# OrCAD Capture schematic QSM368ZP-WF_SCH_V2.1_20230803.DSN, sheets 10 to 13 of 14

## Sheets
10 PAGE11-UART&CAN: size A2
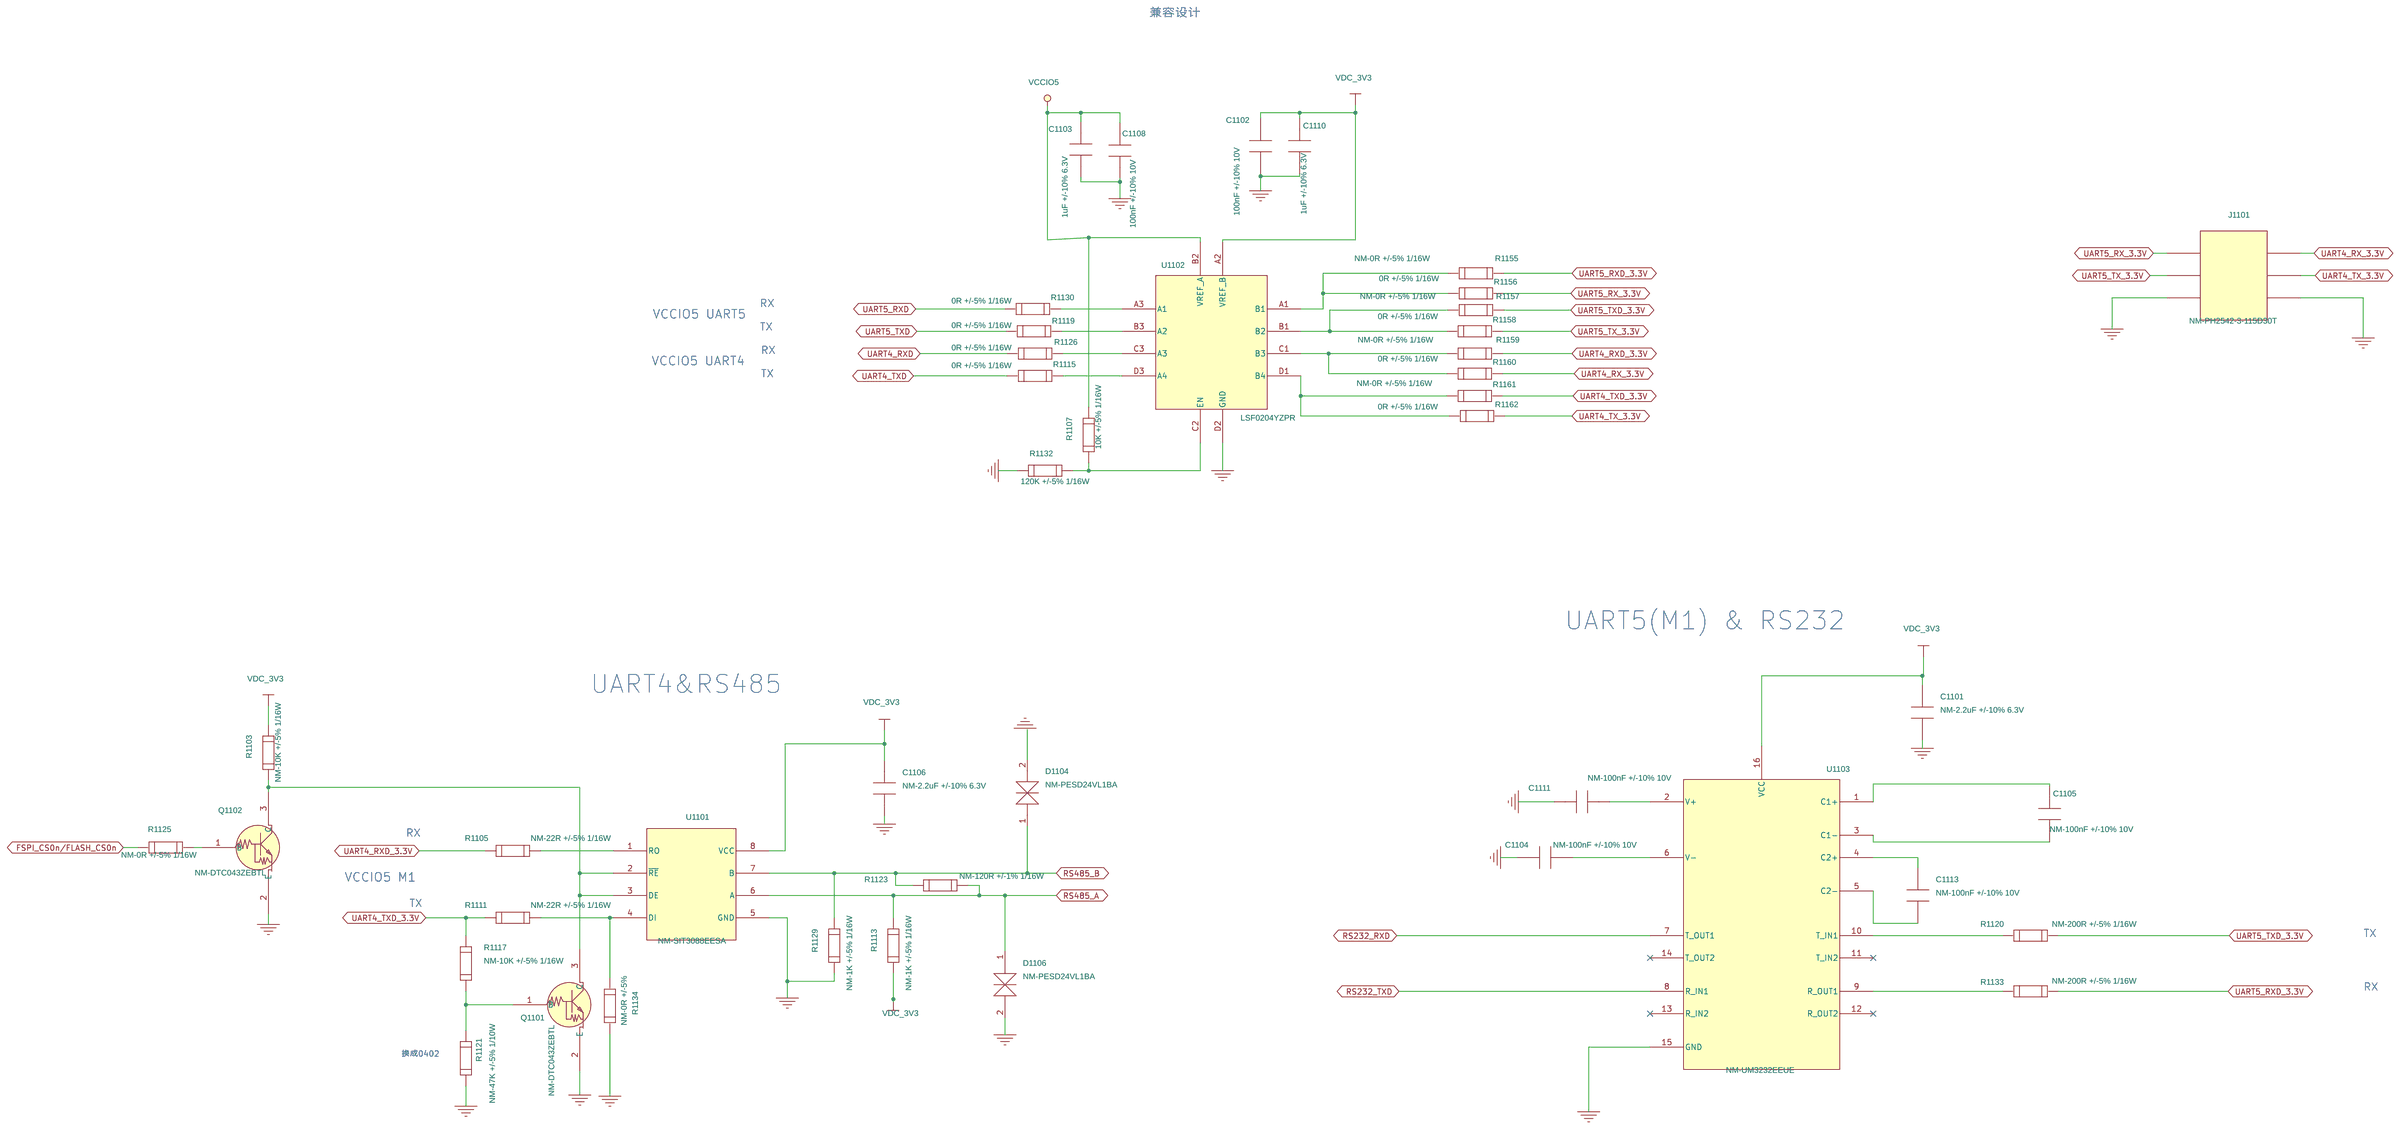
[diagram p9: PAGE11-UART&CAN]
11 PAGE12-RTC&KEY: size A3
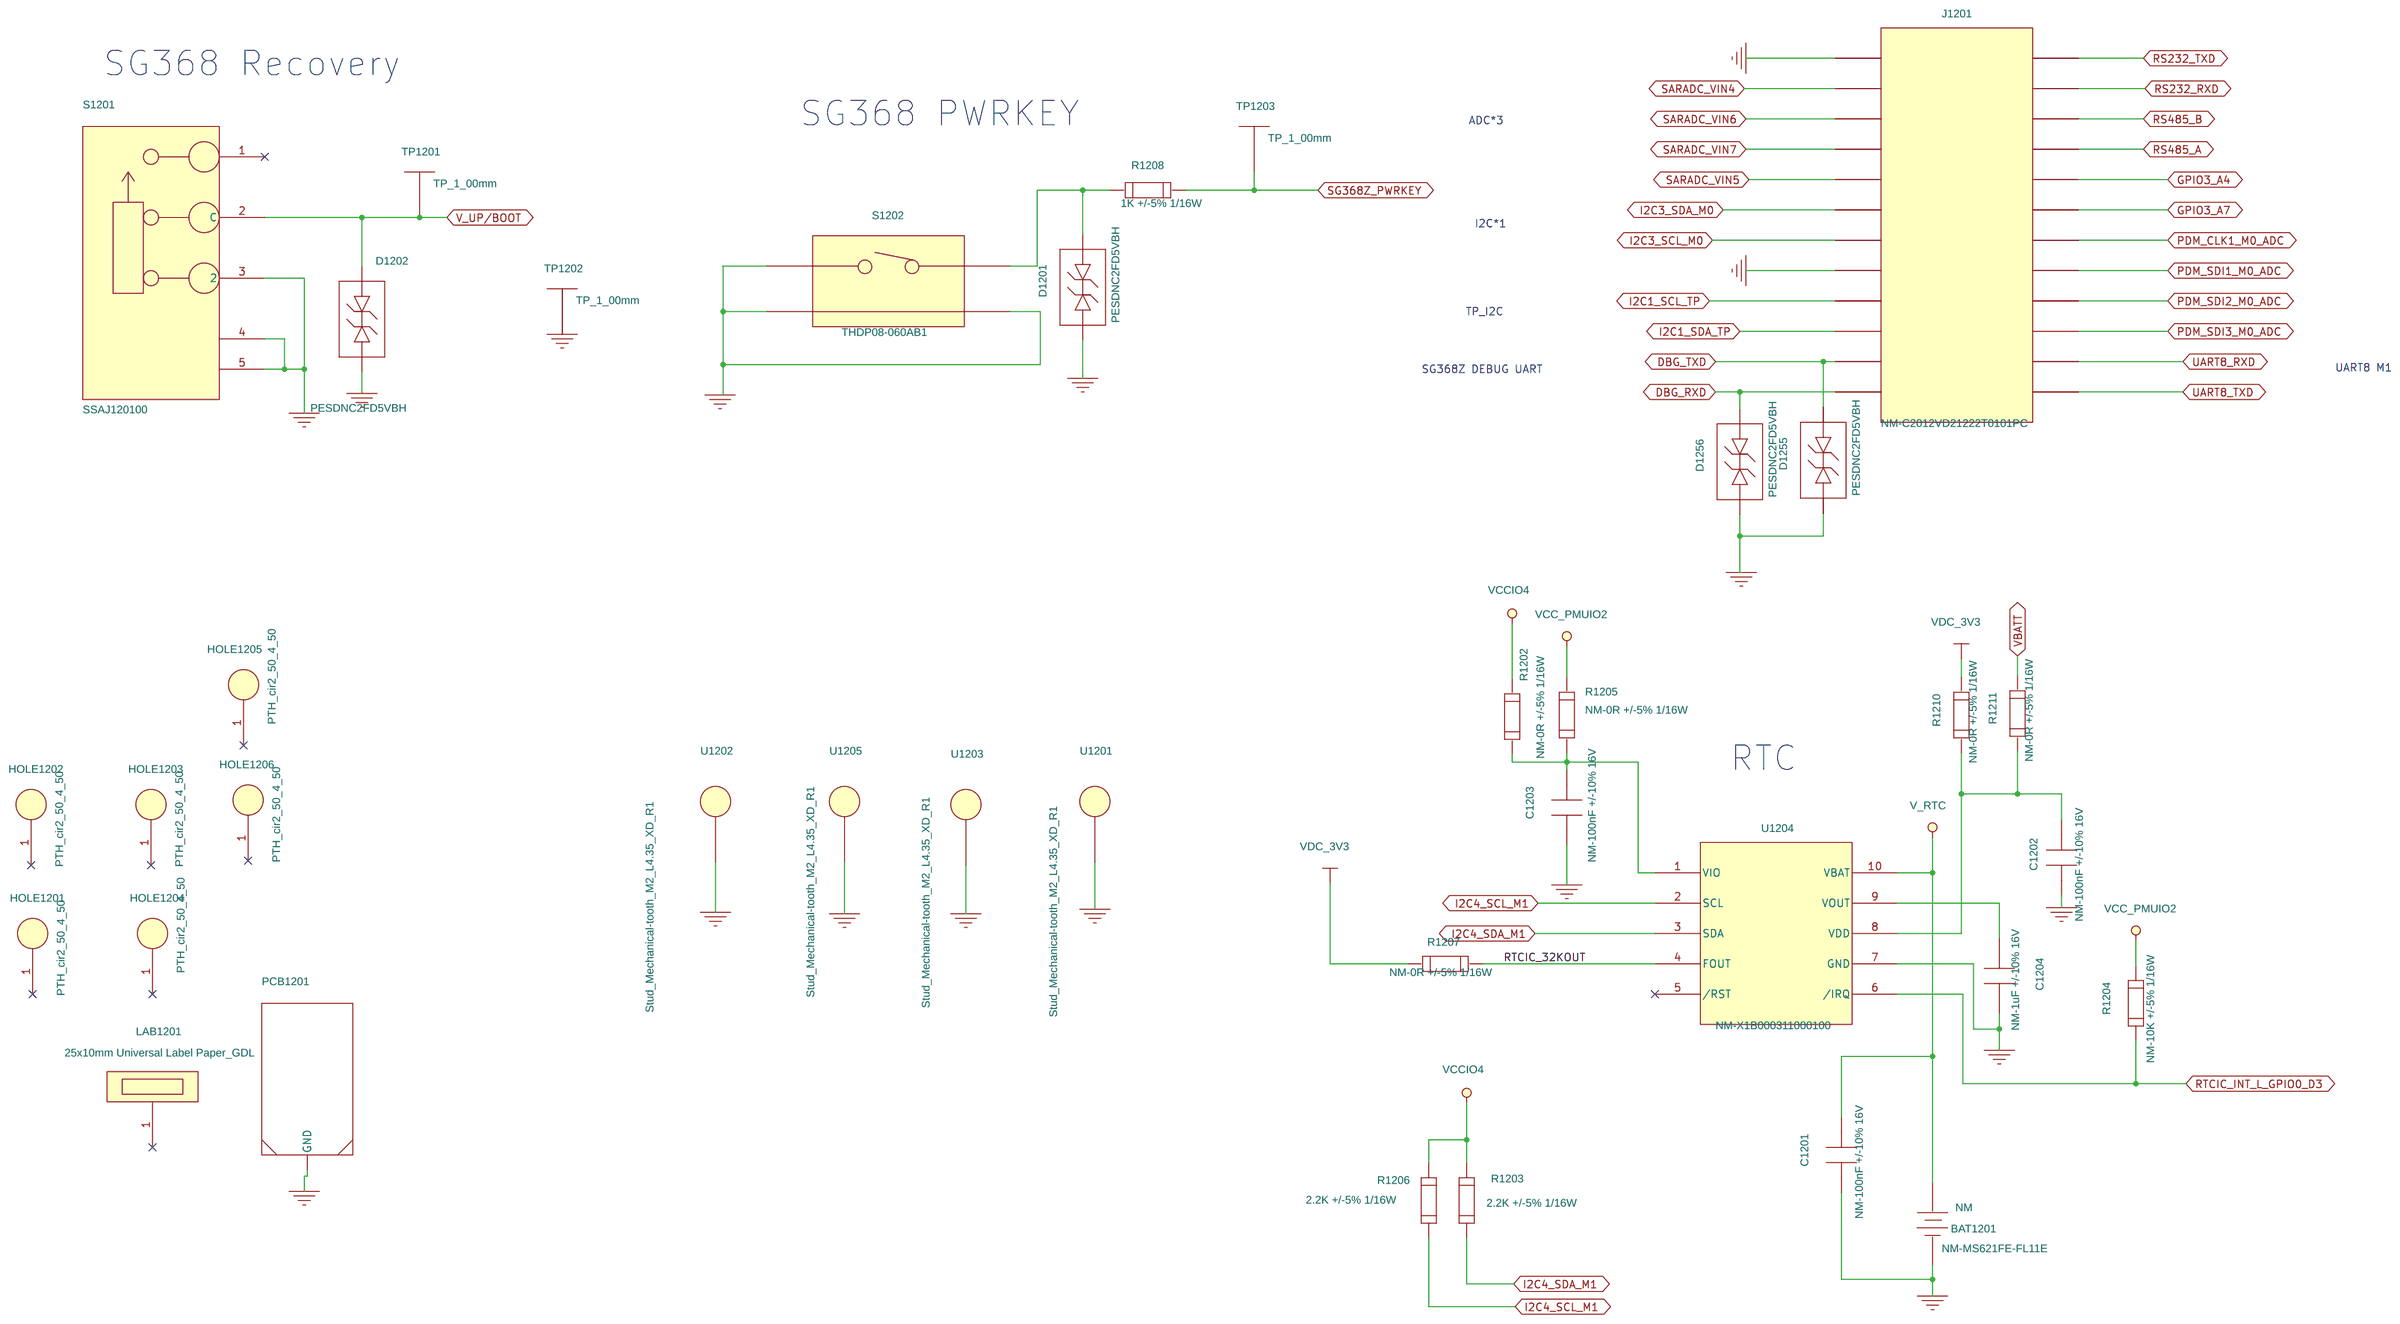
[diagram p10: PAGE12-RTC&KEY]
12 PAGE13-Module1: size A2
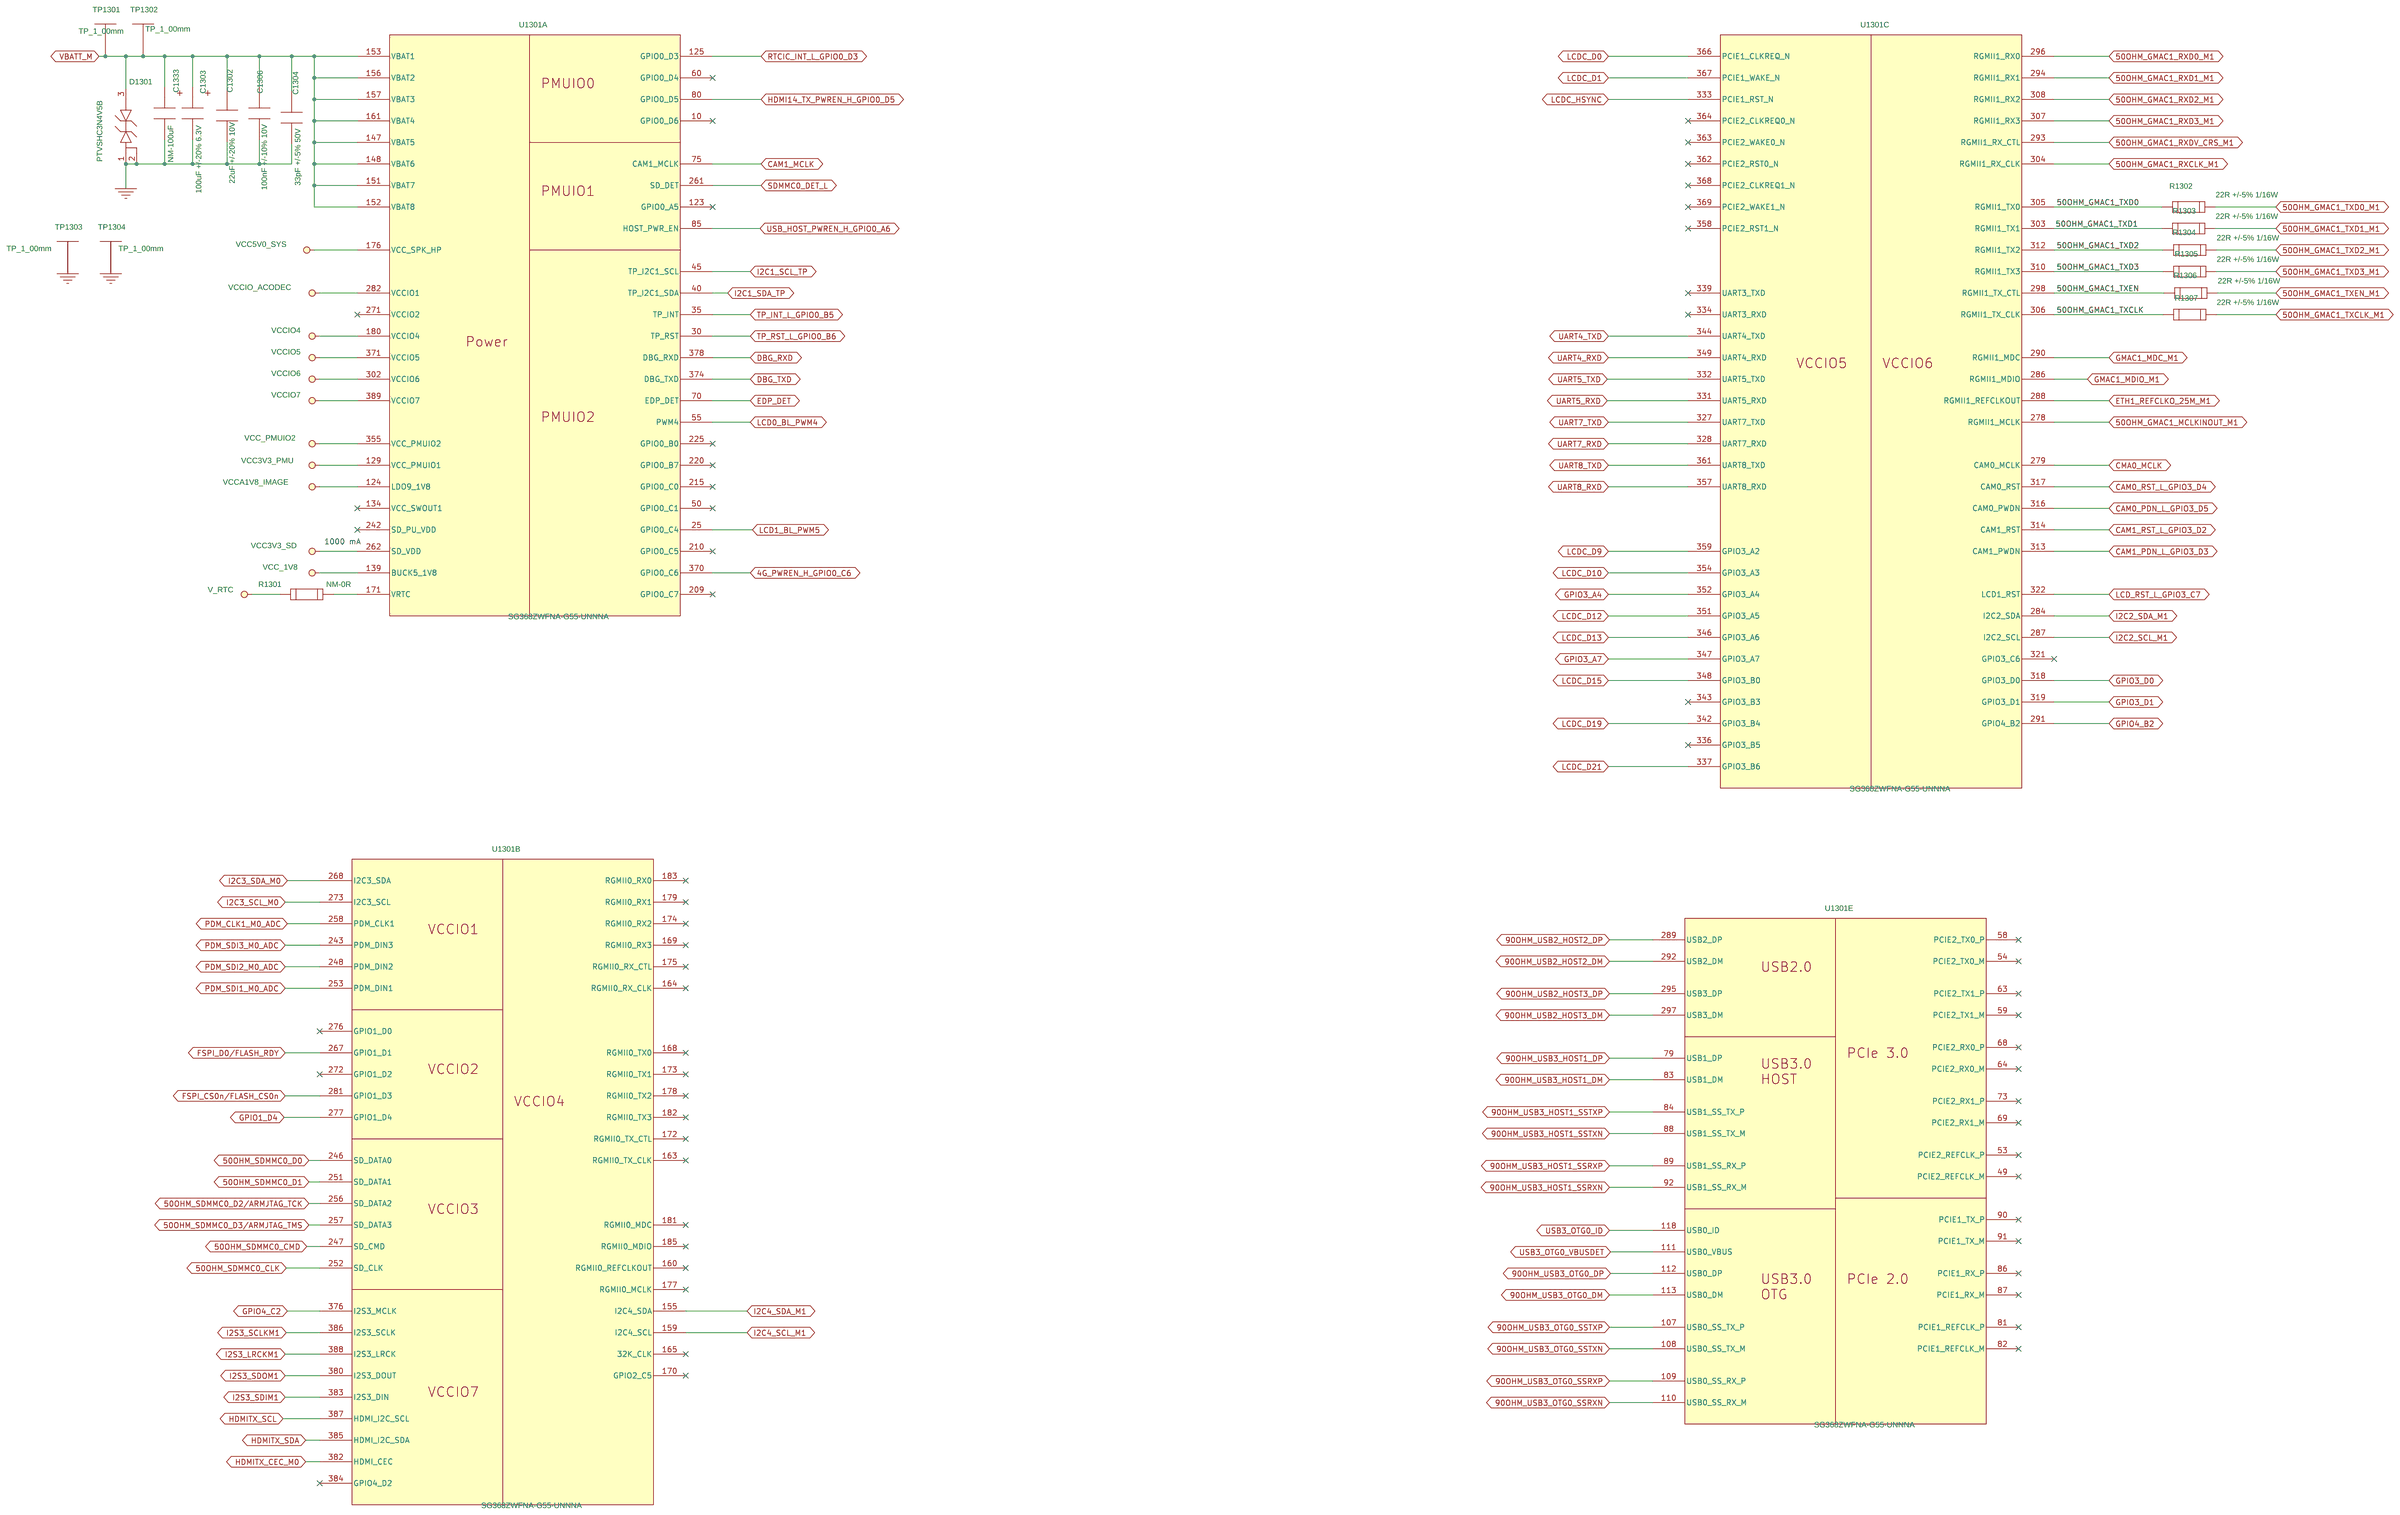
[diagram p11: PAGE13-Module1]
13 PAGE14-Module2: size A2
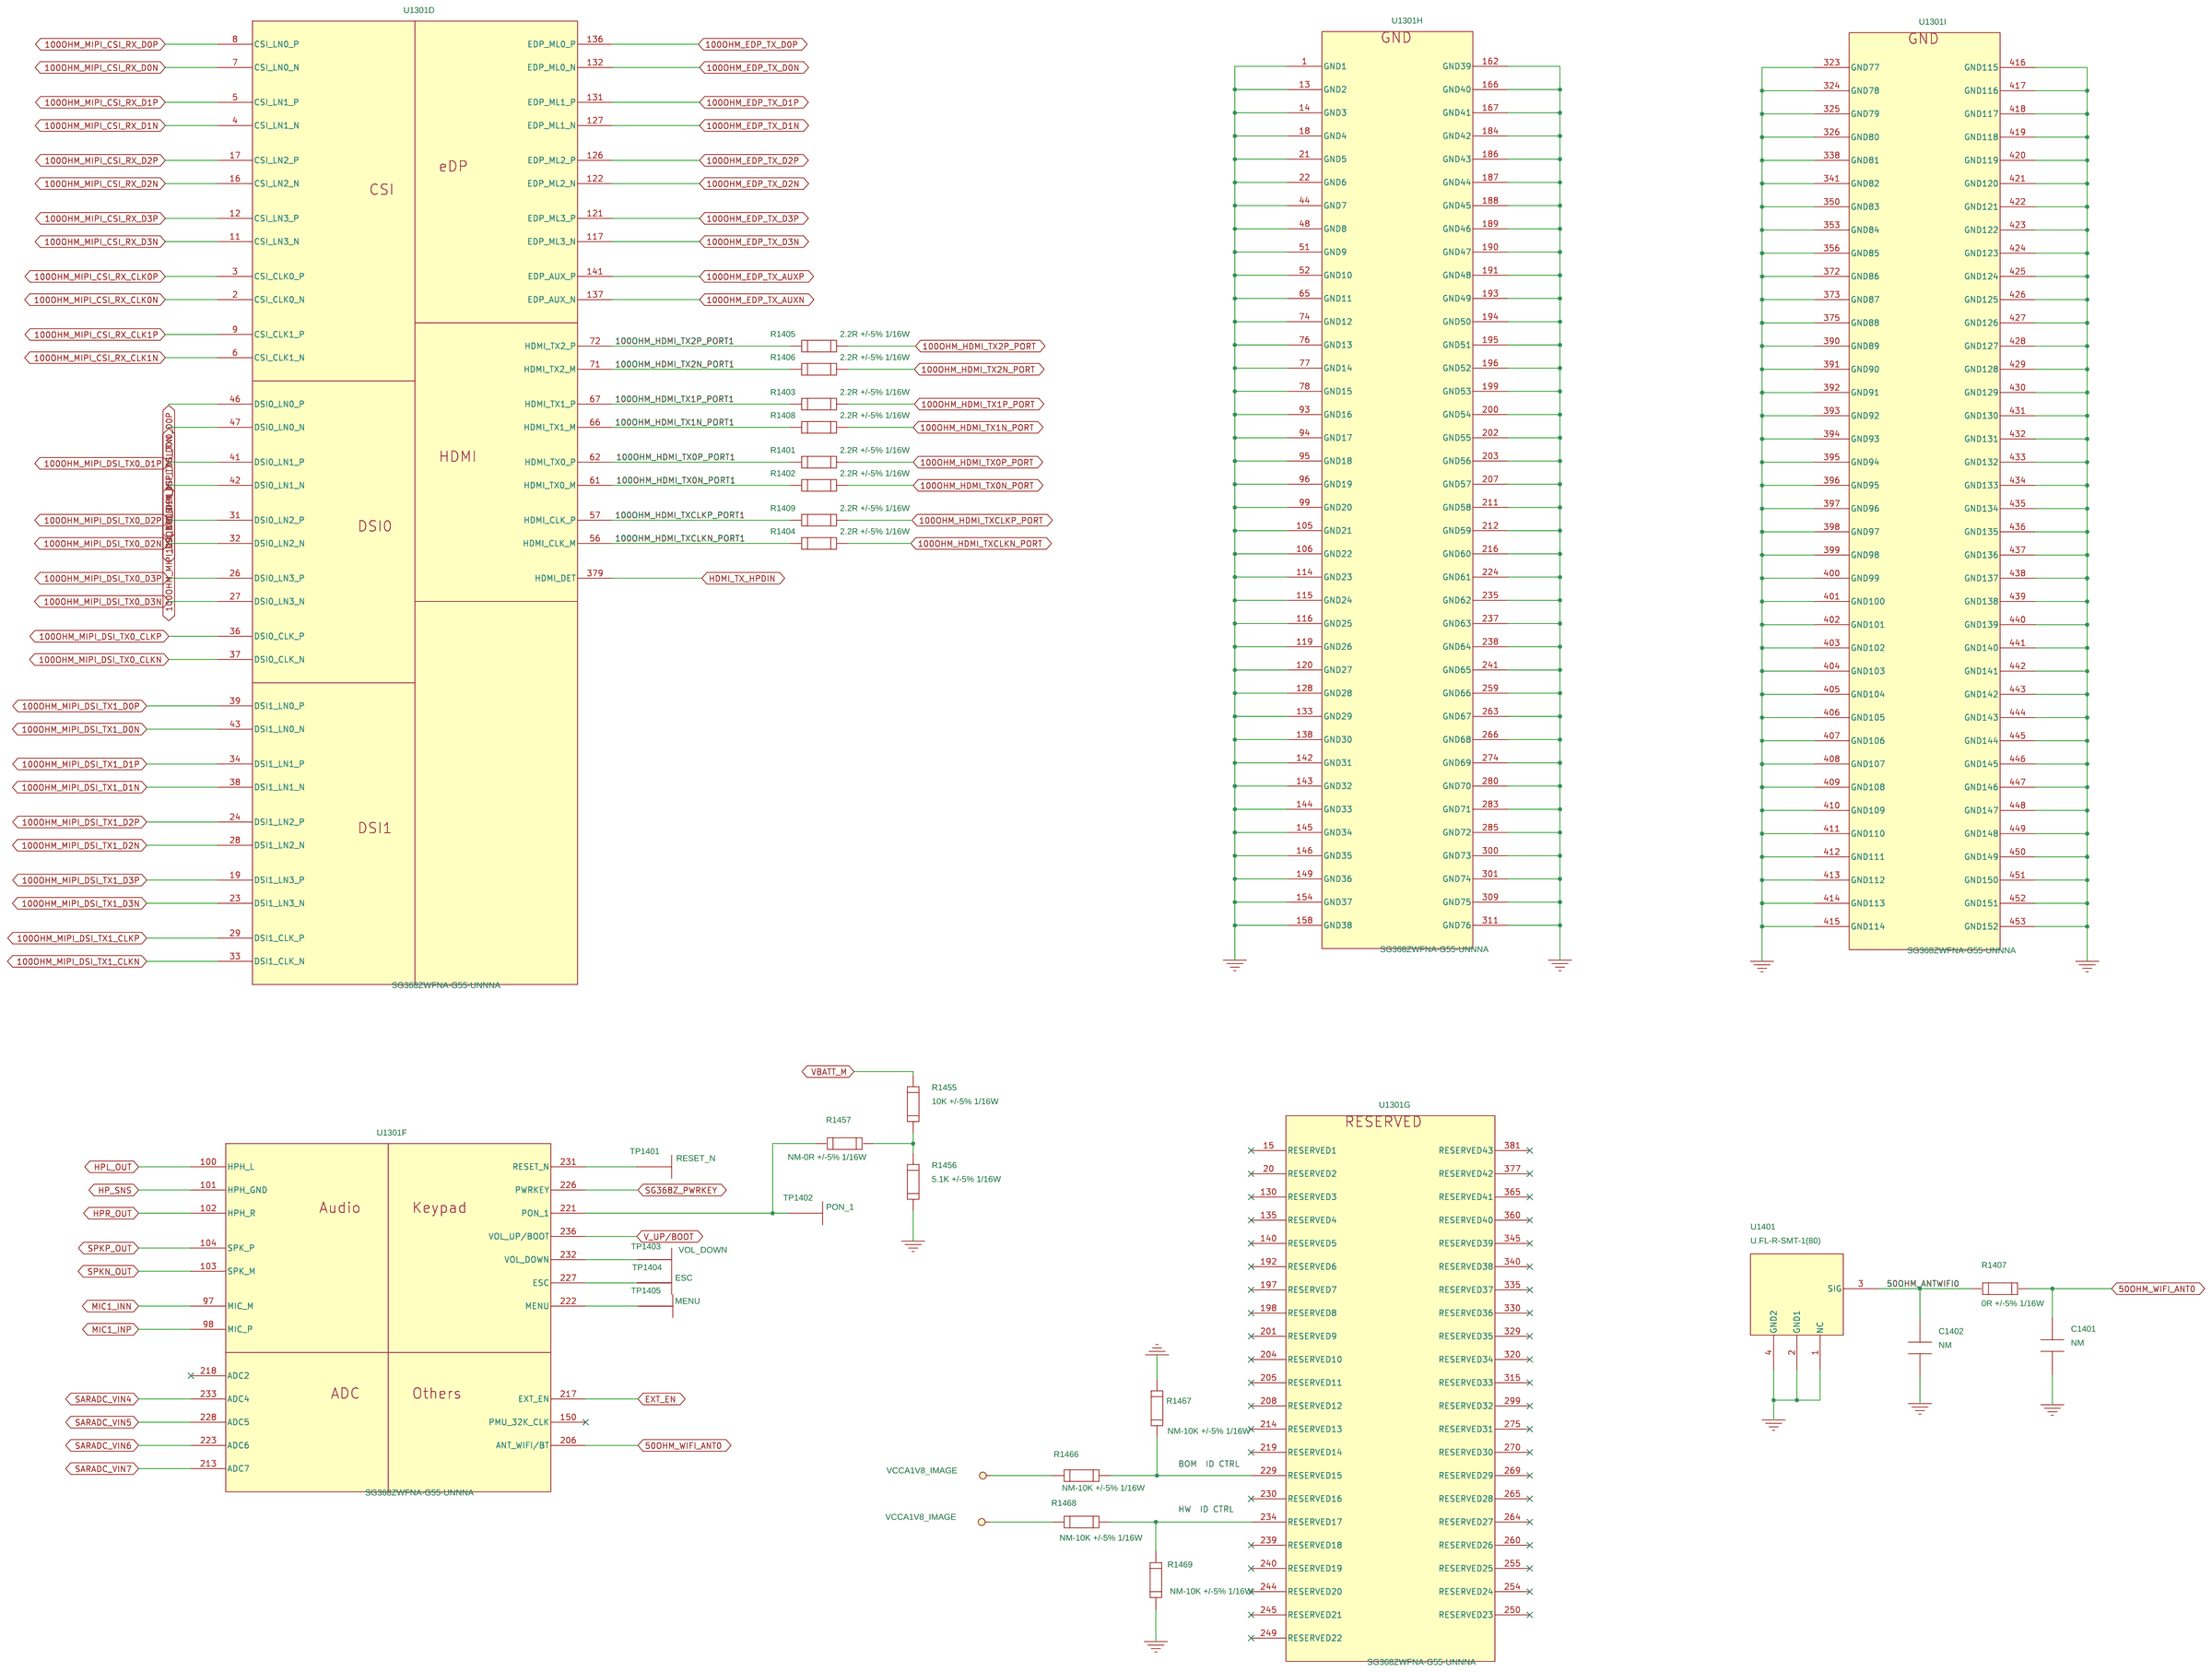
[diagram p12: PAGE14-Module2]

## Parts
sheet PAGE11-UART&CAN
C1101  NM-2.2uF +/-10% 6.3V  [c-0402]
C1102  100nF +/-10% 10V  [C-0402]
C1103  1uF +/-10% 6.3V  [C-0402]
C1104  NM-100nF +/-10% 10V  [C-0402]
C1105  NM-100nF +/-10% 10V  [C-0402]
C1106  NM-2.2uF +/-10% 6.3V  [c-0402]
C1108  100nF +/-10% 10V  [C-0402]
C1110  1uF +/-10% 6.3V  [C-0402]
C1111  NM-100nF +/-10% 10V  [C-0402]
C1113  NM-100nF +/-10% 10V  [C-0402]
D1104  NM-PESD24VL1BA  [SOD-323]
D1106  NM-PESD24VL1BA  [SOD-323]
J1101  NM-PH2542-3-115D30T  [PH2542-3-115D30T]
Q1101  NM-DTC043ZEBTL  [DTC043ZEBTL]
Q1102  NM-DTC043ZEBTL  [DTC043ZEBTL]
R1103  NM-10K +/-5% 1/16W  [R-0402]
R1105  NM-22R +/-5% 1/16W  [R-0402]
R1107  10K +/-5% 1/16W  [R-0402]
R1111  NM-22R +/-5% 1/16W  [R-0402]
R1113  NM-1K +/-5% 1/16W  [R-0402]
R1115  0R +/-5% 1/16W  [R-0402]
R1117  NM-10K +/-5% 1/16W  [R-0402]
R1119  0R +/-5% 1/16W  [R-0402]
R1120  NM-200R +/-5% 1/16W  [R-0402]
R1121  NM-47K +/-5% 1/10W  [R-0603]
R1123  NM-120R +/-1% 1/16W  [R-0402]
R1125  NM-0R +/-5% 1/16W  [R-0402]
R1126  0R +/-5% 1/16W  [R-0402]
R1129  NM-1K +/-5% 1/16W  [R-0402]
R1130  0R +/-5% 1/16W  [R-0402]
R1132  120K +/-5% 1/16W  [R-0402]
R1133  NM-200R +/-5% 1/16W  [R-0402]
R1134  NM-0R +/-5%  [R-0402]
R1155  NM-0R +/-5% 1/16W  [R-0402]
R1156  0R +/-5% 1/16W  [R-0402]
R1157  NM-0R +/-5% 1/16W  [R-0402]
R1158  0R +/-5% 1/16W  [R-0402]
R1159  NM-0R +/-5% 1/16W  [R-0402]
R1160  0R +/-5% 1/16W  [R-0402]
R1161  NM-0R +/-5% 1/16W  [R-0402]
R1162  0R +/-5% 1/16W  [R-0402]
U1101  NM-SIT3088EESA  [SIT3088EESA]
U1102  LSF0204YZPR  [LSF0204YZPR]
U1103  NM-UM3232EEUE  [UM3232EEUE]
sheet PAGE12-RTC&KEY
BAT1201  NM-MS621FE-FL11E  [MS621FE-FL11E]
C1201  NM-100nF +/-10% 16V  [C-0402]
C1202  NM-100nF +/-10% 16V  [C-0402]
C1203  NM-100nF +/-10% 16V  [C-0402]
C1204  NM-1uF +/-10% 16V  [C-0603]
D1201  PESDNC2FD5VBH  [PESDNC2FD5VBH]
D1202  PESDNC2FD5VBH  [PESDNC2FD5VBH]
D1255  PESDNC2FD5VBH  [PESDNC2FD5VBH]
D1256  PESDNC2FD5VBH  [PESDNC2FD5VBH]
HOLE1201  PTH_cir2_50_4_50  [PTH_cir2_50_4_50]
HOLE1202  PTH_cir2_50_4_50  [PTH_cir2_50_4_50]
HOLE1203  PTH_cir2_50_4_50  [PTH_cir2_50_4_50]
HOLE1204  PTH_cir2_50_4_50  [PTH_cir2_50_4_50]
HOLE1205  PTH_cir2_50_4_50  [PTH_cir2_50_4_50]
HOLE1206  PTH_cir2_50_4_50  [PTH_cir2_50_4_50]
J1201  NM-C2012VD21222T0101PC  [C2012VD21222T0101PC]
LAB1201  25x10mm Universal Label Paper_GDL  [SILKLABEL_25_00x10_00]
PCB1201  BOARD_PCB  [BOARD_PCB]
R1202  NM-0R +/-5% 1/16W  [R-0402]
R1203  2.2K +/-5% 1/16W  [R-0402]
R1204  NM-10K +/-5% 1/16W  [R-0402]
R1205  NM-0R +/-5% 1/16W  [R-0402]
R1206  2.2K +/-5% 1/16W  [R-0402]
R1207  NM-0R +/-5% 1/16W  [R-0402]
R1208  1K +/-5% 1/16W  [R-0402]
R1210  NM-0R +/-5% 1/16W  [R-0402]
R1211  NM-0R +/-5% 1/16W  [R-0402]
S1201  SSAJ120100  [SSAJ120100]
S1202  THDP08-060AB1  [THDP08-060AB1_PINS4_7D5X8D7]
TP1201  TP_1_00mm  [TP_1_00]
TP1202  TP_1_00mm  [TP_1_00]
TP1203  TP_1_00mm  [TP_1_00]
U1201  Stud_Mechanical-tooth_M2_L4.35_XD_R1  [tp-nuu-m3_15x6_00x4_35mm]
U1202  Stud_Mechanical-tooth_M2_L4.35_XD_R1  [tp-nuu-m3_15x6_00x4_35mm]
U1203  Stud_Mechanical-tooth_M2_L4.35_XD_R1  [tp-nuu-m3_15x6_00x4_35mm]
U1204  NM-X1B000311000100  [X1B000311000100_PINS10_3D2X2D5]
U1205  Stud_Mechanical-tooth_M2_L4.35_XD_R1  [tp-nuu-m3_15x6_00x4_35mm]
sheet PAGE13-Module1
C1302  22uF +/-20% 10V  [c-0603_22_47uf_h1_00]
C1303  100uF +/-20% 6.3V  [3528TB-M]
C1304  33pF +/-5% 50V  [C-0402]
C1306  100nF +/-10% 10V  [C-0402]
C1333  NM-100uF  [3528TB-M]
D1301  PTVSHC3N4V5B  [PTVSHC3N4V5B]
R1301  NM-0R  [R-0402]
R1302  22R +/-5% 1/16W  [R-0402]
R1303  22R +/-5% 1/16W  [R-0402]
R1304  22R +/-5% 1/16W  [R-0402]
R1305  22R +/-5% 1/16W  [R-0402]
R1306  22R +/-5% 1/16W  [R-0402]
R1307  22R +/-5% 1/16W  [R-0402]
TP1301  TP_1_00mm  [TP_1_00]
TP1302  TP_1_00mm  [TP_1_00]
TP1303  TP_1_00mm  [TP_1_00]
TP1304  TP_1_00mm  [TP_1_00]
U1301  SG368ZWFNA-G55-UNNNA  [SG368Z]  (sections A,B,C,D,E,F,G,H,I)
sheet PAGE14-Module2
C1401  NM  [C-0402]
C1402  NM  [C-0402]
R1401  2.2R +/-5% 1/16W  [R-0402]
R1402  2.2R +/-5% 1/16W  [R-0402]
R1403  2.2R +/-5% 1/16W  [R-0402]
R1404  2.2R +/-5% 1/16W  [R-0402]
R1405  2.2R +/-5% 1/16W  [R-0402]
R1406  2.2R +/-5% 1/16W  [R-0402]
R1407  0R +/-5% 1/16W  [R-0402]
R1408  2.2R +/-5% 1/16W  [R-0402]
R1409  2.2R +/-5% 1/16W  [R-0402]
R1455  10K +/-5% 1/16W  [R-0402]
R1456  5.1K +/-5% 1/16W  [R-0402]
R1457  NM-0R +/-5% 1/16W  [R-0402]
R1466  NM-10K +/-5% 1/16W  [R-0402]
R1467  NM-10K +/-5% 1/16W  [R-0402]
R1468  NM-10K +/-5% 1/16W  [R-0402]
R1469  NM-10K +/-5% 1/16W  [R-0402]
TP1401  RESET_N  [TP_1_00]
TP1402  PON_1  [TP_1_00]
TP1403  VOL_DOWN  [TP_1_00]
TP1404  ESC  [TP_1_00]
TP1405  MENU  [TP_1_00]
U1401  U.FL-R-SMT-1(80)  [RF-CON-818000117]

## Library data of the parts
C1101 C1106 = C-0402: Application_Level: 通用; BOMRemark: NM; DataRecord: 2017-08-09; Geometry Height: 0.55mm; Lib_Name: 电容; MPN: CC0402KRX5R5BB225; Part Description: CAP X5R 2.2uF +/-10% 6.3V CH0402 RO; Part Number: QT0012002039; Rev.Date: 2022-08-17
C1102 C1108 = C: Application_Level: Common(通用); DataRecord: 2017-08-09; Geometry Height: 0.5mm; Lib_Name: 电容; MPN: CC0402KRX7R6BB104; Manufacturer: YAGEO; Part Description: CAP X7R 100nF +/-10% 10V CH0402 H0.55mm RO; Part Number: QT0012000328; Rev.Date: 2022-08-17
C1103 C1110 = C: Application_Level: 通用; DataRecord: 2017-08-09; Geometry Height: 0.5mm; Lib_Name: 电容; MPN: CC0402KRX5R5BB105; Manufacturer: YAGEO; Part Description: CAP X5R 1uF +/-10% 6.3V CH0402 H0.55mm RO; Part Number: QT0012100534; Rev.Date: 2022-08-17
C1104 C1105 C1111 C1113 = C: Application_Level: Common(通用); BOMRemark: NM; DataRecord: 2017-08-09; Geometry Height: 0.5mm; Lib_Name: 电容; MPN: CC0402KRX7R6BB104; Manufacturer: YAGEO; Part Description: CAP X7R 100nF +/-10% 10V CH0402 H0.55mm RO; Part Number: QT0012000328; Rev.Date: 2021-12-15
D1104 D1106 = PESD5V0S1BL: BOMRemark: NM; Part Number: QT0013501025
J1101 = PH2542-3-115D30T: Application_Level: 限制（Others）; BOMRemark: NM; DataRecord: 2018-01-03; Geometry Height: 11.5mm; Lib_Name: 结构连接器; Manufacturer: CHANG LONG; Part Description: CON DIP PIN HEADER 2x3PIN 2.54pitch H11.5mm 180° PA6T RO; Part Number: QT0016201042; Rev.Date: 2022-08-17
Q1101 Q1102 = DTC043ZEBTL: Application_Level: Common(通用); BOMRemark: NM; DataRecord: 2017-08-09; Geometry Height: 0.6mm; Lib_Name: 三极管; Manufacturer: ROHM; Part Description: AUD Digital NPN 50V 100mA R1=4.7K R2=47K EMT3F RO; Part Number: QT0015200080; Rev.Date: 2021-12-15
R1103 R1117 R1204 = R-0402: Application_Level: Common(通用); BOMRemark: NM; DataRecord: 2017-08-09; Geometry Height: 0.4MM; Lib_Name: 电阻; MPN: RC0402JR-0710KL; Manufacturer: YAGEO; Part Description: RES MF 10K +/-5% 1/16W CH0402 H0.4mm RO; Part Number: QT0011000453; Rev.Date: 2021-12-15
R1105 R1111 = R-0402: Application_Level: Common(通用); BOMRemark: NM; DataRecord: 2017-08-09; Geometry Height: 0.4MM; Lib_Name: 电阻; MPN: RC0402JR-0722RL; Manufacturer: YAGEO; Part Description: RES MF 22R +/-5% 1/16W CH0402 H0.4mm RO; Part Number: QT0011000603; Rev.Date: 2021-12-15
R1107 = R-0402: Application_Level: Common(通用); DataRecord: 2017-08-09; Geometry Height: 0.4MM; Lib_Name: 电阻; MPN: RC0402JR-0710KL; Manufacturer: YAGEO; Part Description: RES MF 10K +/-5% 1/16W CH0402 H0.4mm RO; Part Number: QT0011000453; Rev.Date: 2022-08-17
R1113 R1129 = R-0402: Application_Level: Common(通用); BOMRemark: NM; DataRecord: 2017-08-09; Geometry Height: 0.4MM; Lib_Name: 电阻; MPN: RC0402JR-071KL; Manufacturer: YAGEO; Part Description: RES MF 1K +/-5% 1/16W CH0402 H0.4mm RO; Part Number: QT0011000489; Rev.Date: 2021-12-15
R1115 R1119 R1126 R1130 R1156 R1158 R1160 R1162 = R-0402_v3: Application_Level: Common(通用); DataRecord: 2017-08-09; Geometry Height: 0.4MM; Lib_Name: 电阻; MPN: RC0402JR-070RL; Manufacturer: YAGEO; Part Description: RES MF 0R +/-5% 1/16W CH0402 H0.4mm RO; Part Number: QT0011000094; Rev.Date: 2022-08-17
R1120 R1133 = R-0402_v3: BOMRemark: NM; Manufacturer: YAGEO; Part Description: RES MF 200R +/-5% 1/16W CH0402 RO; Part Number: QT0011000579
R1121 = R-0603: Application_Level: Common(通用); BOMRemark: NM; DataRecord: 2017-08-09; Geometry Height: 0.55MM; Lib_Name: 电阻; MPN: RC0603JR-070RL; Manufacturer: YAGEO; Part Description: RES MF 47K +/-5% 1/10W CH0603 H0.55mm RO; Part Number: QT0011001077; Rev.Date: 2021-12-15
R1123 = R-0402: Application_Level: Common(通用); BOMRemark: NM; DataRecord: 2018-01-19; Geometry Height: 0.4MM; Lib_Name: 电阻; MPN: RC0402FR-07120RL; Manufacturer: YAGEO; Part Description: RES MF 120R +/-1% 1/16W CH0402 H0.4mm RO; Part Number: QT0011003219; Rev.Date: 2021-12-15
R1125 R1155 R1157 R1159 R1161 R1202 R1205 R1207 R1210 R1211 = R-0402_v3: Application_Level: Common(通用); BOMRemark: NM; DataRecord: 2017-08-09; Geometry Height: 0.4MM; Lib_Name: 电阻; MPN: RC0402JR-070RL; Manufacturer: YAGEO; Part Description: RES MF 0R +/-5% 1/16W CH0402 H0.4mm RO; Part Number: QT0011000094; Rev.Date: 2021-12-15
R1132 = R-0402: Application_Level: Common(通用); DataRecord: 2017-08-09; Geometry Height: 0.4MM; Lib_Name: 电阻; MPN: RC0402JR-07120KL; Manufacturer: YAGEO; Part Description: RES MF 120K +/-5% 1/16W CH0402 H0.4mm RO; Part Number: QT0011000521; Rev.Date: 2022-08-17
R1134 = R-0402_v3: BOMRemark: NM; Manufacturer: YAGEO; Part Description: RES MF 0R +/-5% 1/16W CH0402 RO; Part Number: QT0011000094
U1101 = SIT3088EESA: Application_Level: Common(通用); BOMRemark: NM; DataRecord: 2021-04-29; Geometry Height: 1.7mm; Lib_Name: 驱动芯片; Manufacturer: SITCORES; Part Description: IC RS485 Transceiver 14Mbps 8-SOP H1.7mm RO; Part Number: QT0013901339; Rev.Date: 2021-10-25
U1102 = LSF0204YZPR: Application_Level: 限制（Others）; DataRecord: 2022-01-04; Lib_Name: 基带模拟开关; MPN: AW39114FOR; Manufacturer: AWINIC; Part Description: IC Level Shifier 4-Bit Bidirectional 12-DSBGA 1.87x1.37mm H0.624mm RO; Part Number: QT0013901431; Rev.Date: 2022-08-17
U1103 = UM3232EEUE: Application_Level: 通用; BOMRemark: NM; DataRecord: 2021-09-01; Geometry Height: 1.2mm; Lib_Name: 驱动芯片; Manufacturer: UNION; Part Description: IC RS-232  250kbps 16-TSSOP 4.96x6.4mm H1.2mm RO; Part Number: QT0013901375; Rev.Date: 2022-08-17
BAT1201 = MS621FE-FL11E_0: BOMRemark: NM; Geometry.Height: 2.1mm; Manufacturer: SII; Part Description: BATTERY RECHARGEABLE 3.0V 5.5mAh Φ6.8mm H2.1mm RO; Part Number: QT0014400031
C1201-C1203 = C: Application_Level: 通用; BOMRemark: NM; DataRecord: 2017-08-09; Geometry Height: 0.5mm; Lib_Name: 电容; MPN: CC0402KRX7R7BB104; Manufacturer: YAGEO; Part Description: CAP X7R 100nF +/-10% 16V CH0402 H0.55mm RO; Part Number: QT0012100748; Rev.Date: 2022-08-17
C1204 = C: Application_Level: Limited(限制); BOMRemark: NM; DataRecord: 2017-08-09; Geometry Height: 0.8mm; Lib_Name: 电容; MPN: CC0603KRX5R7BB105; Manufacturer: YAGEO; Part Description: CAP X5R 1uF +/-10% 16V CH0603 H0.9mm RO; Part Number: QT0012000033; Rev.Date: 2021-12-15
D1201 D1255 D1256 = PESDNC2FD5VBH: Application_Level: Common(通用); DataRecord: 2019-11-21; Geometry Height: 0.5mm; Lib_Name: ESD&EMI&TVS; Manufacturer: PRISEMI; Part Description: TVS Bi Vrwm=5V 35pF DFN1006-2L RO; Part Number: QT0013501067; Rev.Date: 2022-09-20
D1202 = PESDNC2FD5VBH: DataRecord: 2019-11-21; Geometry Height: 0.5mm; Lib_Name: ESD&EMI&TVS; Manufacturer: PRISEMI; Part Description: TVS Bi Vrwm=5V 35pF DFN1006-2L RO; Part Number: QT0013501067; Rev.Date: 2022-09-20
HOLE1201-HOLE1206 = PTH_cir2_50_4_50: option: @
J1201 = C2012VD21222T0101PC: Application_Level: 通用; BOMRemark: NM; DataRecord: 2022-05-23; Geometry Height: 7.6mm; Lib_Name: 结构连接器; Manufacturer: KONNRA; Part Description: CON FEMALE HEADER 2x12PIN 2.0pitch H7.6mm 180° RO; Part Number: QT0016201706; Rev.Date: 2022-08-17
LAB1201 = SILKLABEL_25_00x10_00: Application_Level: 通用; BOMRemark: NSMT; DataRecord: 2017-08-09; Geometry Height: 0.15mm; Lib_Name: 标签纸; Manufacturer: KINGDELI; Part Description: Universal 25x10mm plain laber paper GDL RO; Part Number: QT0030700006; Rev.Date: 2022-08-17
PCB1201 = BOARD_PCB: DataRecord: 2023-05-24; MPN: QSM368ZP-WF_PBT1_V1.1_PCB_ZH_R1; Manufacturer: TOPCB; Part Description: PCB QSM368ZP-WF PBT1(X1 Y1) V1.1 4L THR 120x100mm H1.6m ZH RO; Part Number: QT0021104483; Rev.Date: 2023-07-12
R1203 R1206 = R-0402: Application_Level: Common(通用); DataRecord: 2017-08-09; Geometry Height: 0.4MM; Lib_Name: 电阻; MPN: RC0402JR-072K2L; Manufacturer: YAGEO; Part Description: RES MF 2.2K +/-5% 1/16W CH0402 H0.4mm RO; Part Number: QT0011000522; Rev.Date: 2022-08-17
R1208 = R-0402_v3: DataRecord: 2017-08-09; Geometry Height: 0.4MM; MPN: RC0402JR-071KL; Manufacturer: YAGEO; Part Description: RES MF 1K +/-5% 1/16W CH0402 H0.4mm RO; Part Number: QT0011000489; Rev.Date: 2022-08-17
S1201 = SSAJ120100: Application_Level: Limited(限制); DataRecord: 2020-06-22; Geometry Height: 0.7mm; Lib_Name: 机械开关和按键; Manufacturer: ALPS; Part Description: SWITCH SLIDE 6.5x3.8mm H0.7mm RO; Part Number: QT0016401035; Rev.Date: 2021-12-15
S1202 = THDP08-060AB1: Application_Level: Common(通用); BOMRemark: NSMT; DataRecord: 2022-07-08; Geometry Height: 6.3mm; Lib_Name: 机械开关和按键; Manufacturer: ZK-BEST; Part Description: BUTTON TACT PINS4 7.5x8.7mm H6.3mm RO; Part Number: QT0016401098; Rev.Date: 2022-08-17
TP1201-TP1203 TP1301-TP1304 = TP_1_00: option: @
U1201-U1203 U1205 = tp-nuu-m3_15x6_00x4_35mm: DataRecord: 2023-03-16; Geometry Height: 4.45; Lib_Name: 螺丝等紧固件; Manufacturer: SUND; Part Description: Stud Mechanical-tooth M2xL4.35mm D5.5x2mm XD Matte-tin RO; Part Number: QT0020001091; Rev.Date: 2023-03-16
U1204 = X1B000311000100: Application_Level: 通用; BOMRemark: NM; DataRecord: 2020-02-20; Geometry Height: 1.0mm; Lib_Name: 通用处理器; Manufacturer: EPSON; Part Description: IC RTC 10Pin 0.7pitch 3.2x2.5mm H1.0mm RO; Part Number: QT0013201042; Rev.Date: 2022-08-17
C1302 = c-0603_22_47uf_H1_00: Application_Level: 通用; DataRecord: 2017-08-09; Geometry Height: 1.0mm; Lib_Name: 电容; MPN: CC0603MRX5R6BB226; Manufacturer: YAGEO; Part Description: CAP X5R 22uF +/-20% 10V CH0603 1.6x0.8mm H1mm RO; Part Number: QT0012102005; Rev.Date: 2022-09-21
C1303 = C-3528TB-M: DataRecord: 2017-12-12; Geometry Height: 2.1mm; MPN: TCOB0J107M8R-ES1; Manufacturer: ROHM; Part Description: CAP STA Polymer 100uF +/-20% 6.3V ESR=0.045R B CASE 3.5x2.8mm H2.1mm RO; Part Number: QT0012002189; Rev.Date: 2022-09-21; SCH Part: C-TCOB0J107M8R
C1304 = C: Application_Level: Non-common(非通用); DataRecord: 2017-08-09; Geometry Height: 0.5mm; Lib_Name: 电容; MPN: CC0402JRNPO9BN330; Manufacturer: YAGEO; Part Description: CAP C0G 33pF +/-5% 50V CH0402 H0.55mm RO; Part Number: QT0012100261; Rev.Date: 2022-08-17
C1306 = C: DataRecord: 2017-08-09; Geometry Height: 0.5mm; Lib_Name: 电容; MPN: CC0402KRX7R6BB104; Manufacturer: YAGEO; Part Description: CAP X7R 100nF +/-10% 10V CH0402 H0.55mm RO; Part Number: QT0012000328; Rev.Date: 2022-08-17
C1333 = C-3528TB-M: BOMRemark: NM
D1301 = PTVSHC3N4V5B: Application_Level: Common(通用); DataRecord: 2020-06-03; Geometry Height: 0.65mm; Lib_Name: ESD&EMI&TVS; Manufacturer: PRISEMI; Part Description: TVS Bi Vrwm=4.5V 700pF DFN2×2-3L RO; Part Number: QT0013501094; Rev.Date: 2023-03-30
R1301 = R-0402: Application_Level: Common(通用); BOMRemark: NM; DataRecord: 2017-08-09; Geometry Height: 0.4MM; Lib_Name: 电阻; MPN: RC0402JR-070RL; Manufacturer: YAGEO; Part Description: RES MF 0R +/-5% 1/16W CH0402 H0.4mm RO; Part Number: QT0011000094; Rev.Date: 2021-12-15
R1302-R1307 = R-0402: Application_Level: 通用; DataRecord: 2017-08-09; Geometry Height: 0.4MM; Lib_Name: 电阻; MPN: RC0402JR-0722RL; Manufacturer: YAGEO; Part Description: RES MF 22R +/-5% 1/16W CH0402 H0.4mm RO; Part Number: QT0011000603; Rev.Date: 2022-08-17
U1301 = SG368Z
C1401 C1402 = C-0402_X5R_1UF
R1401-R1406 R1408 R1409 = R-0402: Application_Level: 通用; DataRecord: 2021-11-17; Geometry Height: 0.4mm; Lib_Name: 电阻; MPN: RC0402JR-072R2L; Manufacturer: YAGEO; Part Description: RES MF 2.2R +/-5% 1/16W CH0402 H0.4mm RO; Part Number: QT0011004737; Rev.Date: 2022-08-17
R1407 = R-0402_v3: Application_Level: 通用; DataRecord: 2017-08-09; Geometry Height: 0.4MM; Lib_Name: 电阻; MPN: RC0402JR-070RL; Manufacturer: YAGEO; Part Description: RES MF 0R +/-5% 1/16W CH0402 H0.4mm RO; Part Number: QT0011000094; Rev.Date: 2022-08-17
R1455 = R-0402_0R: DataRecord: 2017-08-09; Geometry Height: 0.4MM; MPN: RC0402JR-0710KL; Part Description: RES MF 10K +/-5% 1/16W CH0402 H0.4mm RO; Part Number: QT0011000453; Rev.Date: 2022-08-17
R1456 = R-0402: Application_Level: 通用; DataRecord: 2017-08-09; Geometry Height: 0.4MM; Lib_Name: 电阻; MPN: RC0402JR-075K1L; Manufacturer: YAGEO; Part Description: RES MF 5.1K +/-5% 1/16W CH0402 H0.4mm RO; Part Number: QT0011000142; Rev.Date: 2022-08-17
R1457 = R-0402_v3: Application_Level: 通用; BOMRemark: NM; DataRecord: 2017-08-09; Geometry Height: 0.4MM; Lib_Name: 电阻; MPN: RC0402JR-070RL; Manufacturer: YAGEO; Part Description: RES MF 0R +/-5% 1/16W CH0402 H0.4mm RO; Part Number: QT0011000094; Rev.Date: 2022-08-17
R1466-R1469 = R-0402_0R: BOMRemark: NM; DataRecord: 2017-08-09; Geometry Height: 0.4MM; MPN: RC0402JR-0710KL; Part Description: RES MF 10K +/-5% 1/16W CH0402 H0.4mm RO; Part Number: QT0011000453; Rev.Date: 2021-10-11
TP1401-TP1405 = TP_1_00: BOMRemark: TP_1_00mm; Part Number: TP_1_00mm; option: @
U1401 = RF-CON-818000117: Application_Level: 通用; DataRecord: 2017-11-08; Geometry Height: 1.25mm; Lib_Name: 结构连接器; Manufacturer: HRS; Part Description: CON RFC 2.6x2.6mm H1.25mm RO; Part Number: QT0016201033; Rev.Date: 2022-08-17

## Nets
GND: BAT1201.2 C1101.1 C1102.2 C1103.1 C1104.1 C1106.1 C1108.2 C1110.1 C1111.2 C1201.1 C1202.1 C1203.1 C1204.1 C1302.1 C1303.2 C1304.1 C1306.1 C1333.2 C1401.1 C1402.1 D1104.2 D1106.2 D1201.1 D1202.2 D1255.1 D1256.1 D1301.1 D1301.2 J1101.5 J1101.6 J1201.1 J1201.15 PCB1201.1(GND) Q1101.2(E) Q1102.2(E) R1121.1 R1129.1 R1132.2 R1134.1 R1456.1 R1467.2 R1469.1 S1201.3(2) S1201.4 S1201.5 S1202.1 S1202.3 S1202.4 TP1202.1 TP1303.1 TP1304.1 U1101.5(GND) U1102.D2(GND) U1103.15(GND) U1201.1 U1202.1 U1203.1 U1204.7(GND) U1205.1 U1301.1(GND1) U1301.13(GND2) U1301.14(GND3) U1301.18(GND4) U1301.21(GND5) U1301.22(GND6) U1301.44(GND7) U1301.48(GND8) U1301.51(GND9) U1301.52(GND10) U1301.65(GND11) U1301.74(GND12) U1301.76(GND13) U1301.77(GND14) U1301.78(GND15) U1301.93(GND16) U1301.94(GND17) U1301.95(GND18) U1301.96(GND19) U1301.99(GND20) U1301.105(GND21) U1301.106(GND22) U1301.114(GND23) U1301.115(GND24) U1301.116(GND25) U1301.119(GND26) U1301.120(GND27) U1301.128(GND28) U1301.133(GND29) U1301.138(GND30) U1301.142(GND31) U1301.143(GND32) U1301.144(GND33) U1301.145(GND34) U1301.146(GND35) U1301.149(GND36) U1301.154(GND37) U1301.158(GND38) U1301.162(GND39) U1301.166(GND40) U1301.167(GND41) U1301.184(GND42) U1301.186(GND43) U1301.187(GND44) U1301.188(GND45) U1301.189(GND46) U1301.190(GND47) U1301.191(GND48) U1301.193(GND49) U1301.194(GND50) U1301.195(GND51) U1301.196(GND52) U1301.199(GND53) U1301.200(GND54) U1301.202(GND55) U1301.203(GND56) U1301.207(GND57) U1301.211(GND58) U1301.212(GND59) U1301.216(GND60) U1301.224(GND61) U1301.235(GND62) U1301.237(GND63) U1301.238(GND64) U1301.241(GND65) U1301.259(GND66) U1301.263(GND67) U1301.266(GND68) U1301.274(GND69) U1301.280(GND70) U1301.283(GND71) U1301.285(GND72) U1301.300(GND73) U1301.301(GND74) U1301.309(GND75) U1301.311(GND76) U1301.323(GND77) U1301.324(GND78) U1301.325(GND79) U1301.326(GND80) U1301.338(GND81) U1301.341(GND82) U1301.350(GND83) U1301.353(GND84) U1301.356(GND85) U1301.372(GND86) U1301.373(GND87) U1301.375(GND88) U1301.390(GND89) U1301.391(GND90) U1301.392(GND91) U1301.393(GND92) U1301.394(GND93) U1301.395(GND94) U1301.396(GND95) U1301.397(GND96) U1301.398(GND97) U1301.399(GND98) U1301.400(GND99) U1301.401(GND100) U1301.402(GND101) U1301.403(GND102) U1301.404(GND103) U1301.405(GND104) U1301.406(GND105) U1301.407(GND106) U1301.408(GND107) U1301.409(GND108) U1301.410(GND109) U1301.411(GND110) U1301.412(GND111) U1301.413(GND112) U1301.414(GND113) U1301.415(GND114) U1301.416(GND115) U1301.417(GND116) U1301.418(GND117) U1301.419(GND118) U1301.420(GND119) U1301.421(GND120) U1301.422(GND121) U1301.423(GND122) U1301.424(GND123) U1301.425(GND124) U1301.426(GND125) U1301.427(GND126) U1301.428(GND127) U1301.429(GND128) U1301.430(GND129) U1301.431(GND130) U1301.432(GND131) U1301.433(GND132) U1301.434(GND133) U1301.435(GND134) U1301.436(GND135) U1301.437(GND136) U1301.438(GND137) U1301.439(GND138) U1301.440(GND139) U1301.441(GND140) U1301.442(GND141) U1301.443(GND142) U1301.444(GND143) U1301.445(GND144) U1301.446(GND145) U1301.447(GND146) U1301.448(GND147) U1301.449(GND148) U1301.450(GND149) U1301.451(GND150) U1301.452(GND151) U1301.453(GND152) U1401.1(NC) U1401.2(GND1) U1401.4(GND2) ; also on sheet 1 2 3 4 5 6 7 8 9 14
VBATT: R1211.1 ; also on sheet 1 2 5
VBATT_M: C1302.2 C1303.1 C1304.2 C1306.2 C1333.1 D1301.3 R1455.2 TP1301.1 TP1302.1 U1301.147(VBAT5) U1301.148(VBAT6) U1301.151(VBAT7) U1301.152(VBAT8) U1301.153(VBAT1) U1301.156(VBAT2) U1301.157(VBAT3) U1301.161(VBAT4) ; also on sheet 1
VCC3V3_PMU: U1301.129(VCC_PMUIO1) ; also on sheet 7
VCC3V3_SD: U1301.262(SD_VDD) ; also on sheet 7
VCC5V0_SYS: U1301.176(VCC_SPK_HP) ; also on sheet 1
VCC_1V8: U1301.139(BUCK5_1V8) ; also on sheet 9
VCC_PMUIO2: R1204.2 R1205.1 U1301.355(VCC_PMUIO2) ; also on sheet 5
VCCA1V8_IMAGE: R1466.2 R1468.2 U1301.124(LDO9_1V8) ; also on sheet 5
VCCIO4: R1202.1 R1203.2 R1206.2 U1301.180(VCCIO4) ; also on sheet 4
VCCIO5: C1103.2 C1108.1 R1107.2 U1102.B2(VREF_A) U1301.371(VCCIO5) ; also on sheet 9 14
VCCIO6: U1301.302(VCCIO6) ; also on sheet 8
VCCIO7: U1301.389(VCCIO7) ; also on sheet 4
VCCIO_ACODEC: U1301.282(VCCIO1) ; also on sheet 4 9
4G_PWREN_H_GPIO0_C6: U1301.370(GPIO0_C6) ; also on sheet 5
50OHM_ANTWIFI0: C1402.2 R1407.2 U1401.3(SIG)
50OHM_GMAC1_MCLKINOUT_M1: U1301.278(RGMII1_MCLK) ; also on sheet 8
50OHM_GMAC1_RXCLK_M1: U1301.304(RGMII1_RX_CLK) ; also on sheet 8
50OHM_GMAC1_RXD0_M1: U1301.296(RGMII1_RX0) ; also on sheet 8
50OHM_GMAC1_RXD1_M1: U1301.294(RGMII1_RX1) ; also on sheet 8
50OHM_GMAC1_RXD2_M1: U1301.308(RGMII1_RX2) ; also on sheet 8
50OHM_GMAC1_RXD3_M1: U1301.307(RGMII1_RX3) ; also on sheet 8
50OHM_GMAC1_RXDV_CRS_M1: U1301.293(RGMII1_RX_CTL) ; also on sheet 8
50OHM_GMAC1_TXCLK: R1307.2 U1301.306(RGMII1_TX_CLK)
50OHM_GMAC1_TXCLK_M1: R1307.1 ; also on sheet 8
50OHM_GMAC1_TXD0: R1302.2 U1301.305(RGMII1_TX0)
50OHM_GMAC1_TXD0_M1: R1302.1 ; also on sheet 8
50OHM_GMAC1_TXD1: R1303.2 U1301.303(RGMII1_TX1)
50OHM_GMAC1_TXD1_M1: R1303.1 ; also on sheet 8
50OHM_GMAC1_TXD2: R1304.2 U1301.312(RGMII1_TX2)
50OHM_GMAC1_TXD2_M1: R1304.1 ; also on sheet 8
50OHM_GMAC1_TXD3: R1305.2 U1301.310(RGMII1_TX3)
50OHM_GMAC1_TXD3_M1: R1305.1 ; also on sheet 8
50OHM_GMAC1_TXEN: R1306.2 U1301.298(RGMII1_TX_CTL)
50OHM_GMAC1_TXEN_M1: R1306.1 ; also on sheet 8
50OHM_SDMMC0_CLK: U1301.252(SD_CLK) ; also on sheet 7
50OHM_SDMMC0_CMD: U1301.247(SD_CMD) ; also on sheet 7
50OHM_SDMMC0_D0: U1301.246(SD_DATA0) ; also on sheet 7
50OHM_SDMMC0_D1: U1301.251(SD_DATA1) ; also on sheet 7
50OHM_SDMMC0_D2/ARMJTAG_TCK: U1301.256(SD_DATA2) ; also on sheet 7
50OHM_SDMMC0_D3/ARMJTAG_TMS: U1301.257(SD_DATA3) ; also on sheet 7
50OHM_WIFI_ANT0: C1401.2 R1407.1 U1301.206(ANT_WIFI/BT)
90OHM_USB2_HOST2_DM: U1301.292(USB2_DM) ; also on sheet 6
90OHM_USB2_HOST2_DP: U1301.289(USB2_DP) ; also on sheet 6
90OHM_USB2_HOST3_DM: U1301.297(USB3_DM) ; also on sheet 6
90OHM_USB2_HOST3_DP: U1301.295(USB3_DP) ; also on sheet 6
90OHM_USB3_HOST1_DM: U1301.83(USB1_DM) ; also on sheet 6
90OHM_USB3_HOST1_DP: U1301.79(USB1_DP) ; also on sheet 6
90OHM_USB3_HOST1_SSRXN: U1301.92(USB1_SS_RX_M) ; also on sheet 3
90OHM_USB3_HOST1_SSRXP: U1301.89(USB1_SS_RX_P) ; also on sheet 3
90OHM_USB3_HOST1_SSTXN: U1301.88(USB1_SS_TX_M) ; also on sheet 3
90OHM_USB3_HOST1_SSTXP: U1301.84(USB1_SS_TX_P) ; also on sheet 3
90OHM_USB3_OTG0_DM: U1301.113(USB0_DM) ; also on sheet 3
90OHM_USB3_OTG0_DP: U1301.112(USB0_DP) ; also on sheet 3
90OHM_USB3_OTG0_SSRXN: U1301.110(USB0_SS_RX_M) ; also on sheet 3
90OHM_USB3_OTG0_SSRXP: U1301.109(USB0_SS_RX_P) ; also on sheet 3
90OHM_USB3_OTG0_SSTXN: U1301.108(USB0_SS_TX_M) ; also on sheet 3
90OHM_USB3_OTG0_SSTXP: U1301.107(USB0_SS_TX_P) ; also on sheet 3
100OHM_EDP_TX_AUXN: U1301.137(EDP_AUX_N) ; also on sheet 5
100OHM_EDP_TX_AUXP: U1301.141(EDP_AUX_P) ; also on sheet 5
100OHM_EDP_TX_D0N: U1301.132(EDP_ML0_N) ; also on sheet 5
100OHM_EDP_TX_D0P: U1301.136(EDP_ML0_P) ; also on sheet 5
100OHM_EDP_TX_D1N: U1301.127(EDP_ML1_N) ; also on sheet 5
100OHM_EDP_TX_D1P: U1301.131(EDP_ML1_P) ; also on sheet 5
100OHM_EDP_TX_D2N: U1301.122(EDP_ML2_N) ; also on sheet 5
100OHM_EDP_TX_D2P: U1301.126(EDP_ML2_P) ; also on sheet 5
100OHM_EDP_TX_D3N: U1301.117(EDP_ML3_N) ; also on sheet 5
100OHM_EDP_TX_D3P: U1301.121(EDP_ML3_P) ; also on sheet 5
100OHM_HDMI_TX0N_PORT: R1402.2 ; also on sheet 4
100OHM_HDMI_TX0N_PORT1: R1402.1 U1301.61(HDMI_TX0_M)
100OHM_HDMI_TX0P_PORT: R1401.2 ; also on sheet 4
100OHM_HDMI_TX0P_PORT1: R1401.1 U1301.62(HDMI_TX0_P)
100OHM_HDMI_TX1N_PORT: R1408.2 ; also on sheet 4
100OHM_HDMI_TX1N_PORT1: R1408.1 U1301.66(HDMI_TX1_M)
100OHM_HDMI_TX1P_PORT: R1403.2 ; also on sheet 4
100OHM_HDMI_TX1P_PORT1: R1403.1 U1301.67(HDMI_TX1_P)
100OHM_HDMI_TX2N_PORT: R1406.2 ; also on sheet 4
100OHM_HDMI_TX2N_PORT1: R1406.1 U1301.71(HDMI_TX2_M)
100OHM_HDMI_TX2P_PORT: R1405.2 ; also on sheet 4
100OHM_HDMI_TX2P_PORT1: R1405.1 U1301.72(HDMI_TX2_P)
100OHM_HDMI_TXCLKN_PORT: R1404.2 ; also on sheet 4
100OHM_HDMI_TXCLKN_PORT1: R1404.1 U1301.56(HDMI_CLK_M)
100OHM_HDMI_TXCLKP_PORT: R1409.2 ; also on sheet 4
100OHM_HDMI_TXCLKP_PORT1: R1409.1 U1301.57(HDMI_CLK_P)
100OHM_MIPI_CSI_RX_CLK0N: U1301.2(CSI_CLK0_N) ; also on sheet 2
100OHM_MIPI_CSI_RX_CLK0P: U1301.3(CSI_CLK0_P) ; also on sheet 2
100OHM_MIPI_CSI_RX_CLK1N: U1301.6(CSI_CLK1_N) ; also on sheet 2
100OHM_MIPI_CSI_RX_CLK1P: U1301.9(CSI_CLK1_P) ; also on sheet 2
100OHM_MIPI_CSI_RX_D0N: U1301.7(CSI_LN0_N) ; also on sheet 2
100OHM_MIPI_CSI_RX_D0P: U1301.8(CSI_LN0_P) ; also on sheet 2
100OHM_MIPI_CSI_RX_D1N: U1301.4(CSI_LN1_N) ; also on sheet 2
100OHM_MIPI_CSI_RX_D1P: U1301.5(CSI_LN1_P) ; also on sheet 2
100OHM_MIPI_CSI_RX_D2N: U1301.16(CSI_LN2_N) ; also on sheet 2
100OHM_MIPI_CSI_RX_D2P: U1301.17(CSI_LN2_P) ; also on sheet 2
100OHM_MIPI_CSI_RX_D3N: U1301.11(CSI_LN3_N) ; also on sheet 2
100OHM_MIPI_CSI_RX_D3P: U1301.12(CSI_LN3_P) ; also on sheet 2
100OHM_MIPI_DSI_TX0_CLKN: U1301.37(DSI0_CLK_N) ; also on sheet 4
100OHM_MIPI_DSI_TX0_CLKP: U1301.36(DSI0_CLK_P) ; also on sheet 4
100OHM_MIPI_DSI_TX0_D0N: U1301.47(DSI0_LN0_N) ; also on sheet 4
100OHM_MIPI_DSI_TX0_D0P: U1301.46(DSI0_LN0_P) ; also on sheet 4
100OHM_MIPI_DSI_TX0_D1N: U1301.42(DSI0_LN1_N) ; also on sheet 4
100OHM_MIPI_DSI_TX0_D1P: U1301.41(DSI0_LN1_P) ; also on sheet 4
100OHM_MIPI_DSI_TX0_D2N: U1301.32(DSI0_LN2_N) ; also on sheet 4
100OHM_MIPI_DSI_TX0_D2P: U1301.31(DSI0_LN2_P) ; also on sheet 4
100OHM_MIPI_DSI_TX0_D3N: U1301.27(DSI0_LN3_N) ; also on sheet 4
100OHM_MIPI_DSI_TX0_D3P: U1301.26(DSI0_LN3_P) ; also on sheet 4
100OHM_MIPI_DSI_TX1_CLKN: U1301.33(DSI1_CLK_N) ; also on sheet 5
100OHM_MIPI_DSI_TX1_CLKP: U1301.29(DSI1_CLK_P) ; also on sheet 5
100OHM_MIPI_DSI_TX1_D0N: U1301.43(DSI1_LN0_N) ; also on sheet 5
100OHM_MIPI_DSI_TX1_D0P: U1301.39(DSI1_LN0_P) ; also on sheet 5
100OHM_MIPI_DSI_TX1_D1N: U1301.38(DSI1_LN1_N) ; also on sheet 5
100OHM_MIPI_DSI_TX1_D1P: U1301.34(DSI1_LN1_P) ; also on sheet 5
100OHM_MIPI_DSI_TX1_D2N: U1301.28(DSI1_LN2_N) ; also on sheet 5
100OHM_MIPI_DSI_TX1_D2P: U1301.24(DSI1_LN2_P) ; also on sheet 5
100OHM_MIPI_DSI_TX1_D3N: U1301.23(DSI1_LN3_N) ; also on sheet 5
100OHM_MIPI_DSI_TX1_D3P: U1301.19(DSI1_LN3_P) ; also on sheet 5
CAM0_PDN_L_GPIO3_D5: U1301.316(CAM0_PWDN) ; also on sheet 2
CAM0_RST_L_GPIO3_D4: U1301.317(CAM0_RST) ; also on sheet 2
CAM1_MCLK: U1301.75(CAM1_MCLK) ; also on sheet 2
CAM1_PDN_L_GPIO3_D3: U1301.313(CAM1_PWDN) ; also on sheet 2
CAM1_RST_L_GPIO3_D2: U1301.314(CAM1_RST) ; also on sheet 2
CMA0_MCLK: U1301.279(CAM0_MCLK) ; also on sheet 2
DBG_RXD: D1256.2 J1201.23 U1301.378(DBG_RXD)
DBG_TXD: D1255.2 J1201.21 U1301.374(DBG_TXD)
EDP_DET: U1301.70(EDP_DET) ; also on sheet 5
ETH1_REFCLKO_25M_M1: U1301.288(RGMII1_REFCLKOUT) ; also on sheet 8
EXT_EN: U1301.217(EXT_EN) ; also on sheet 1 5 6
FSPI_CS0n/FLASH_CS0n: R1125.2 U1301.281(GPIO1_D3)
FSPI_D0/FLASH_RDY: U1301.267(GPIO1_D1) ; also on sheet 5
GMAC1_MDC_M1: U1301.290(RGMII1_MDC) ; also on sheet 8
GMAC1_MDIO_M1: U1301.286(RGMII1_MDIO) ; also on sheet 8
GPIO1_D4: U1301.277(GPIO1_D4) ; also on sheet 14
GPIO3_A4: J1201.10 U1301.352(GPIO3_A4) ; also on sheet 14
GPIO3_A7: J1201.12 U1301.347(GPIO3_A7)
GPIO3_D0: U1301.318(GPIO3_D0) ; also on sheet 14
GPIO3_D1: U1301.319(GPIO3_D1) ; also on sheet 5
GPIO4_B2: U1301.291(GPIO4_B2) ; also on sheet 8
GPIO4_C2: U1301.376(I2S3_MCLK) ; also on sheet 14
HDMI14_TX_PWREN_H_GPIO0_D5: U1301.80(GPIO0_D5) ; also on sheet 4
HDMI_TX_HPDIN: U1301.379(HDMI_DET) ; also on sheet 4
HDMITX_CEC_M0: U1301.382(HDMI_CEC) ; also on sheet 4
HDMITX_SCL: U1301.387(HDMI_I2C_SCL) ; also on sheet 4
HDMITX_SDA: U1301.385(HDMI_I2C_SDA) ; also on sheet 4
HP_SNS: U1301.101(HPH_GND) ; also on sheet 9
HPL_OUT: U1301.100(HPH_L) ; also on sheet 9
HPR_OUT: U1301.102(HPH_R) ; also on sheet 9
I2C1_SCL_TP: J1201.17 U1301.45(TP_I2C1_SCL) ; also on sheet 5
I2C1_SDA_TP: J1201.19 U1301.40(TP_I2C1_SDA) ; also on sheet 5
I2C2_SCL_M1: U1301.287(I2C2_SCL) ; also on sheet 2
I2C2_SDA_M1: U1301.284(I2C2_SDA) ; also on sheet 2
I2C3_SCL_M0: J1201.13 U1301.273(I2C3_SCL) ; also on sheet 2
I2C3_SDA_M0: J1201.11 U1301.268(I2C3_SDA) ; also on sheet 2
I2C4_SCL_M1: R1206.1 U1204.2(SCL) U1301.159(I2C4_SCL) ; also on sheet 4
I2C4_SDA_M1: R1203.1 U1204.3(SDA) U1301.155(I2C4_SDA) ; also on sheet 4
I2S3_LRCKM1: U1301.388(I2S3_LRCK) ; also on sheet 14
I2S3_SCLKM1: U1301.386(I2S3_SCLK) ; also on sheet 14
I2S3_SDIM1: U1301.383(I2S3_DIN) ; also on sheet 14
I2S3_SDOM1: U1301.380(I2S3_DOUT) ; also on sheet 14
LCD0_BL_PWM4: U1301.55(PWM4) ; also on sheet 4
LCD1_BL_PWM5: U1301.25(GPIO0_C4) ; also on sheet 5
LCD_RST_L_GPIO3_C7: U1301.322(LCD1_RST) ; also on sheet 5
LCDC_D0: U1301.366(PCIE1_CLKREQ_N) ; also on sheet 2
LCDC_D1: U1301.367(PCIE1_WAKE_N) ; also on sheet 5
LCDC_D9: U1301.359(GPIO3_A2) ; also on sheet 2
LCDC_D10: U1301.354(GPIO3_A3) ; also on sheet 2
LCDC_D12: U1301.351(GPIO3_A5) ; also on sheet 2
LCDC_D13: U1301.346(GPIO3_A6) ; also on sheet 9
LCDC_D15: U1301.348(GPIO3_B0) ; also on sheet 8
LCDC_D19: U1301.342(GPIO3_B4) ; also on sheet 9
LCDC_D21: U1301.337(GPIO3_B6) ; also on sheet 4
LCDC_HSYNC: U1301.333(PCIE1_RST_N) ; also on sheet 3
MIC1_INN: U1301.97(MIC_M) ; also on sheet 9
MIC1_INP: U1301.98(MIC_P) ; also on sheet 9
PDM_CLK1_M0_ADC: J1201.14 U1301.258(PDM_CLK1)
PDM_SDI1_M0_ADC: J1201.16 U1301.253(PDM_DIN1) ; also on sheet 4
PDM_SDI2_M0_ADC: J1201.18 U1301.248(PDM_DIN2) ; also on sheet 4
PDM_SDI3_M0_ADC: J1201.20 U1301.243(PDM_DIN3)
RS232_RXD: J1201.4 U1103.7(T_OUT1)
RS232_TXD: J1201.2 U1103.8(R_IN1)
RS485_A: D1106.1 J1201.8 R1113.2 R1123.2 U1101.6(A)
RS485_B: D1104.1 J1201.6 R1123.1 R1129.2 U1101.7(B)
RTCIC_32KOUT: R1207.1 U1204.4(FOUT)
RTCIC_INT_L_GPIO0_D3: R1204.1 U1204.6(/IRQ) U1301.125(GPIO0_D3)
SARADC_VIN4: J1201.3 U1301.233(ADC4)
SARADC_VIN5: J1201.9 U1301.228(ADC5)
SARADC_VIN6: J1201.5 U1301.223(ADC6)
SARADC_VIN7: J1201.7 U1301.213(ADC7) ; also on sheet 5
SDMMC0_DET_L: U1301.261(SD_DET) ; also on sheet 7
SG368Z_PWRKEY: R1208.1 TP1203.1 U1301.226(PWRKEY)
SPKN_OUT: U1301.103(SPK_M) ; also on sheet 9
SPKP_OUT: U1301.104(SPK_P) ; also on sheet 9
TP_INT_L_GPIO0_B5: U1301.35(TP_INT) ; also on sheet 5
TP_RST_L_GPIO0_B6: U1301.30(TP_RST) ; also on sheet 5
UART4_RX_3.3V: J1101.2 R1160.2
UART4_RXD: R1126.1 U1301.349(UART4_RXD)
UART4_RXD_3.3V: R1105.1 R1159.1
UART4_TX_3.3V: J1101.4 R1162.2
UART4_TXD: R1115.2 U1301.344(UART4_TXD)
UART4_TXD_3.3V: R1111.1 R1117.1 R1161.1
UART5_RX_3.3V: J1101.1 R1156.2
UART5_RXD: R1130.1 U1301.331(UART5_RXD)
UART5_RXD_3.3V: R1133.2 R1155.1
UART5_TX_3.3V: J1101.3 R1158.2
UART5_TXD: R1119.1 U1301.332(UART5_TXD)
UART5_TXD_3.3V: R1120.2 R1157.1
UART7_RXD: U1301.328(UART7_RXD) ; also on sheet 14
UART7_TXD: U1301.327(UART7_TXD) ; also on sheet 14
UART8_RXD: J1201.22 U1301.357(UART8_RXD)
UART8_TXD: J1201.24 U1301.361(UART8_TXD)
USB3_OTG0_ID: U1301.118(USB0_ID) ; also on sheet 3
USB3_OTG0_VBUSDET: U1301.111(USB0_VBUS) ; also on sheet 3
USB_HOST_PWREN_H_GPIO0_A6: U1301.85(HOST_PWR_EN) ; also on sheet 6
V_RTC: BAT1201.1 C1201.2 R1301.2 U1204.10(VBAT)
V_UP/BOOT: D1202.1 S1201.2(C) TP1201.1 U1301.236(VOL_UP/BOOT)
VDC_3V3: C1101.2 C1102.1 C1106.2 C1110.2 R1103.2 R1113.1 R1207.2 R1210.1 U1101.8(VCC) U1102.A2(VREF_B) U1103.16(VCC) ; also on sheet 1 4 5 8
N16829674: C1111.1 U1103.2(V+)
N16829682: C1104.2 U1103.6(V-)
N16829803: R1120.1 U1103.10(T_IN1)
N16830150: R1111.2 R1134.2 U1101.4(DI)
N16830180: R1105.2 U1101.1(RO)
N16830190: Q1101.3(C) Q1102.3(C) R1103.1 U1101.2(~{RE}) U1101.3(DE)
N16979946: R1107.1 R1132.1 U1102.C2(EN)
N16980060: R1115.1 U1102.D3(A4)
N16980062: R1130.2 U1102.A3(A1)
N16980064: R1126.2 U1102.C3(A3)
N16980078: R1119.2 U1102.B3(A2)
N17308117: D1201.2 R1208.2 S1202.2
N17593444: C1203.2 R1202.2 R1205.2 U1204.1(VIO)
N17594281: C1204.2 U1204.9(VOUT)
N17594510: C1202.2 R1210.2 R1211.2 U1204.8(VDD)
N18191565: Q1101.1(B) R1117.2 R1121.2
N18198024: Q1102.1(B) R1125.1
N18582530: R1301.1 U1301.171(VRTC)
N18603622: TP1401.1 U1301.231(RESET_N)
N18646162: TP1403.1 U1301.232(VOL_DOWN)
N18646180: TP1404.1 U1301.227(ESC)
N18646198: TP1405.1 U1301.222(MENU)
N18646284: R1457.2 TP1402.1 U1301.221(PON_1)
N18920153: R1468.1 R1469.2 U1301.234(RESERVED17)
N18932423: R1455.1 R1456.2 R1457.1
N19051361: C1113.1 U1103.4(C2+)
N19051366: C1113.2 U1103.5(C2-)
N19051381: C1105.1 U1103.1(C1+)
N19051390: C1105.2 U1103.3(C1-)
N19051717: R1133.1 U1103.9(R_OUT1)
N19156624: R1155.2 R1156.1 U1102.A1(B1)
N19156735: R1157.2 R1158.1 U1102.B1(B2)
N19156807: R1159.2 R1160.1 U1102.C1(B3)
N19156822: R1161.2 R1162.1 U1102.D1(B4)
N19197680: R1466.1 R1467.1 U1301.229(RESERVED15)

Not connected (* = marked no-connect by the designer): HOLE1201 1*; HOLE1202 1*; HOLE1203 1*; HOLE1204 1*; HOLE1205 1*; HOLE1206 1*; LAB1201 1*; S1201 1*; U1103 11(T_IN2)* 12(R_OUT2)* 13(R_IN2)* 14(T_OUT2)*; U1204 5(/RST)*; U1301 10(GPIO0_D6)* 15(RESERVED1)* 20(RESERVED2)* 49(PCIE2_REFCLK_M)* 50(GPIO0_C1)* 53(PCIE2_REFCLK_P)* 54(PCIE2_TX0_M)* 58(PCIE2_TX0_P)* 59(PCIE2_TX1_M)* 60(GPIO0_D4)* 63(PCIE2_TX1_P)* 64(PCIE2_RX0_M)* 68(PCIE2_RX0_P)* 69(PCIE2_RX1_M)* 73(PCIE2_RX1_P)* 81(PCIE1_REFCLK_P)* 82(PCIE1_REFCLK_M)* 86(PCIE1_RX_P)* 87(PCIE1_RX_M)* 90(PCIE1_TX_P)* 91(PCIE1_TX_M)* 123(GPIO0_A5)* 130(RESERVED3)* 134(VCC_SWOUT1)* 135(RESERVED4)* 140(RESERVED5)* 150(PMU_32K_CLK)* 160(RGMII0_REFCLKOUT)* 163(RGMII0_TX_CLK)* 164(RGMII0_RX_CLK)* 165(32K_CLK)* 168(RGMII0_TX0)* 169(RGMII0_RX3)* 170(GPIO2_C5)* 172(RGMII0_TX_CTL)* 173(RGMII0_TX1)* 174(RGMII0_RX2)* 175(RGMII0_RX_CTL)* 177(RGMII0_MCLK)* 178(RGMII0_TX2)* 179(RGMII0_RX1)* 181(RGMII0_MDC)* 182(RGMII0_TX3)* 183(RGMII0_RX0)* 185(RGMII0_MDIO)* 192(RESERVED6)* 197(RESERVED7)* 198(RESERVED8)* 201(RESERVED9)* 204(RESERVED10)* 205(RESERVED11)* 208(RESERVED12)* 209(GPIO0_C7)* 210(GPIO0_C5)* 214(RESERVED13)* 215(GPIO0_C0)* 218(ADC2)* 219(RESERVED14)* 220(GPIO0_B7)* 225(GPIO0_B0)* 230(RESERVED16)* 239(RESERVED18)* 240(RESERVED19)* 242(SD_PU_VDD)* 244(RESERVED20)* 245(RESERVED21)* 249(RESERVED22)* 250(RESERVED23)* 254(RESERVED24)* 255(RESERVED25)* 260(RESERVED26)* 264(RESERVED27)* 265(RESERVED28)* 269(RESERVED29)* 270(RESERVED30)* 271(VCCIO2)* 272(GPIO1_D2)* 275(RESERVED31)* 276(GPIO1_D0)* 299(RESERVED32)* 315(RESERVED33)* 320(RESERVED34)* 321(GPIO3_C6)* 329(RESERVED35)* 330(RESERVED36)* 334(UART3_RXD)* 335(RESERVED37)* 336(GPIO3_B5)* 339(UART3_TXD)* 340(RESERVED38)* 343(GPIO3_B3)* 345(RESERVED39)* 358(PCIE2_RST1_N)* 360(RESERVED40)* 362(PCIE2_RST0_N)* 363(PCIE2_WAKE0_N)* 364(PCIE2_CLKREQ0_N)* 365(RESERVED41)* 368(PCIE2_CLKREQ1_N)* 369(PCIE2_WAKE1_N)* 377(RESERVED42)* 381(RESERVED43)* 384(GPIO4_D2)*

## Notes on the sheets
sheet 10
- 兼容设计
- RX
- VCCIO5 UART5
- TX
- RX
- VCCIO5 UART4
- TX
- UART5(M1) & RS232
- UART4&RS485
- RX
- VCCIO5 M1
- TX
- TX
- RX
- 换成0402
sheet 11
- SG368 Recovery
- SG368 PWRKEY
- ADC*3
- I2C*1
- TP_I2C
- SG368Z DEBUG UART
- UART8 M1
- RTC
sheet 12
- 1000 mA
sheet 13
- BOM  ID CTRL
- HW  ID CTRL
